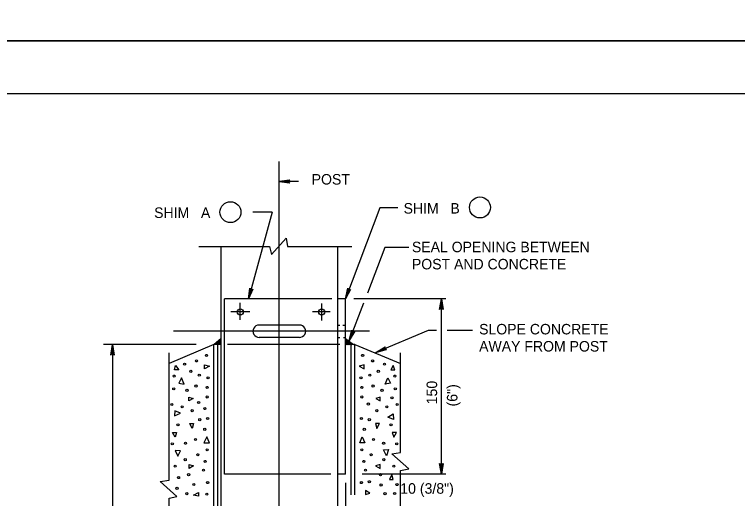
# Model space of a CAD drawing. Extents: x -1958 to 628, y -879 to 309.
# Drawn here: x -1413.6 to -1207.8, y -414.8 to -277.1 of the extents above; entities that cross this region are included whole.
import ezdxf

# ---------------------------------------------------------------- set-up
doc = ezdxf.new("R2010")
doc.units = 0
for name, color, linetype in [('1', 7, 'Continuous'), ('2', 7, 'Continuous'), ('3', 7, 'Continuous'), ('PLT-BNDY', 7, 'Continuous')]:
    doc.layers.add(name, color=color, linetype=linetype)

msp = doc.modelspace()

# ---------------------------------------------------------------- linework, layer by layer
at = {"layer": '1'}
msp.add_line((-1918.39, -299.56), (-1132.39, -299.56), dxfattribs=at)
at = {"layer": '2'}
for p, q in [((-1340.52, -345.33), (-1336.27, -340.7)), ((-1336.27, -340.7), (-1335.89, -343.08)), ((-1361.14, -343.08), (-1341.02, -343.08)), ((-1354.77, -458.72), (-1354.77, -343.08)), ((-1341.02, -343.08), (-1340.52, -345.33)), ((-1335.89, -343.08), (-1317.64, -343.08)), ((-1321.64, -519.58), (-1321.64, -343.08)), ((-1323.27, -357.95), (-1353.89, -357.95)), ((-1353.89, -407.83), (-1353.89, -357.95)), ((-1319.39, -357.95), (-1321.64, -357.95)), ((-1319.39, -407.83), (-1319.39, -357.95)), ((-1349.39, -363.95), (-1349.39, -359.08)), ((-1326.14, -364.08), (-1326.14, -359.33)), ((-1346.64, -361.7), (-1352.02, -361.7)), ((-1323.77, -361.7), (-1328.77, -361.7)), ((-1332.52, -365.45), (-1344.02, -365.45)), ((-1321.64, -365.45), (-1321.02, -365.45)), ((-1320.14, -365.45), (-1319.39, -365.45)), ((-1312.64, -367.2), (-1368.39, -367.2)), ((-1354.77, -369.2), (-1356.77, -370.95)), ((-1354.77, -369.45), (-1356.52, -370.95)), ((-1354.77, -369.83), (-1356.27, -370.95)), ((-1354.77, -370.08), (-1355.89, -370.83)), ((-1354.77, -370.33), (-1355.64, -370.95)), ((-1332.52, -368.95), (-1344.02, -368.95)), ((-1321.64, -368.95), (-1321.02, -368.95)), ((-1320.02, -368.95), (-1319.39, -368.95)), ((-1319.39, -369.2), (-1317.14, -370.95)), ((-1319.39, -369.45), (-1317.52, -370.95)), ((-1319.39, -369.83), (-1317.89, -370.95)), ((-1319.39, -370.08), (-1318.27, -370.95)), ((-1319.39, -370.33), (-1318.52, -370.95)), ((-1356.89, -370.95), (-1369.64, -376.33)), ((-1354.77, -370.95), (-1356.89, -370.95)), ((-1356.89, -458.72), (-1356.89, -370.95)), ((-1355.77, -458.63), (-1355.77, -370.95)), ((-1354.77, -370.58), (-1355.27, -370.83)), ((-1354.77, -370.83), (-1355.02, -370.95)), ((-1321.02, -370.95), (-1353.02, -370.95)), ((-1319.39, -370.58), (-1318.89, -370.95)), ((-1319.39, -370.83), (-1319.27, -370.95)), ((-1316.77, -370.95), (-1319.39, -370.95)), ((-1317.77, -413.7), (-1317.77, -370.95)), ((-1316.77, -370.95), (-1303.77, -376.33)), ((-1316.77, -413.7), (-1316.77, -370.95)), ((-1369.64, -409.58), (-1369.64, -373.33)), ((-1303.77, -401.7), (-1303.77, -373.33)), ((-1306.27, -402.08), (-1303.77, -401.7)), ((-1301.39, -406.33), (-1306.27, -402.08)), ((-1303.77, -406.83), (-1301.39, -406.33)), ((-1303.77, -451.2), (-1303.77, -406.83)), ((-1323.64, -407.83), (-1353.89, -407.83)), ((-1319.39, -407.83), (-1321.64, -407.83)), ((-1372.14, -409.95), (-1369.64, -409.58)), ((-1367.39, -414.2), (-1372.14, -409.95)), ((-1369.64, -414.7), (-1367.39, -414.2)), ((-1369.64, -460.08), (-1369.64, -414.7))]:
    msp.add_line(p, q, dxfattribs=at)
for points in [[(-1366.89, -378.2), (-1368.14, -378.2), (-1367.77, -376.95)], [(-1359.52, -377.83), (-1359.52, -376.7), (-1358.14, -377.08)], [(-1314.14, -377.83), (-1314.14, -376.7), (-1315.52, -377.08)], [(-1306.52, -378.2), (-1305.39, -378.2), (-1305.89, -376.95)], [(-1366.89, -381.95), (-1365.39, -382.2), (-1366.14, -380.45)], [(-1306.64, -381.95), (-1308.14, -382.2), (-1307.39, -380.45)], [(-1364.02, -386.95), (-1364.02, -385.95), (-1362.77, -386.33)], [(-1309.52, -386.95), (-1309.52, -385.95), (-1310.77, -386.33)], [(-1368.02, -389.83), (-1368.14, -391.2), (-1366.39, -390.45)], [(-1305.89, -390.7), (-1305.77, -392.33), (-1307.39, -391.58)], [(-1363.77, -393.45), (-1362.64, -393.45), (-1363.02, -394.83)], [(-1309.77, -393.45), (-1310.89, -393.45), (-1310.52, -394.83)], [(-1368.64, -395.95), (-1367.52, -395.95), (-1367.89, -397.33)], [(-1359.77, -398.95), (-1358.14, -398.95), (-1358.89, -397.2)], [(-1313.89, -398.95), (-1315.39, -398.95), (-1314.64, -397.2)], [(-1304.89, -395.95), (-1306.14, -395.95), (-1305.64, -397.33)], [(-1366.39, -401.2), (-1367.89, -401.08), (-1367.14, -402.7)], [(-1308.64, -400.95), (-1307.14, -400.83), (-1307.77, -402.58)], [(-1363.89, -406.2), (-1363.89, -405.08), (-1362.64, -405.45)], [(-1309.52, -406.2), (-1309.52, -405.08), (-1310.89, -405.45)], [(-1306.89, -409.33), (-1305.89, -409.33), (-1306.27, -407.95)], [(-1361.27, -413.08), (-1361.27, -414.08), (-1362.64, -413.83)], [(-1313.77, -412.45), (-1313.77, -413.58), (-1312.52, -413.2)]]:
    msp.add_lwpolyline(points, close=True, dxfattribs=at)
for centre, radius in [((-1349.36, -361.69), 0.856), ((-1326.19, -361.69), 0.856), ((-1359.01, -374.05), 0.301), ((-1314.54, -374.05), 0.301), ((-1365.22, -376.56), 0.301), ((-1361.85, -375.62), 0.301), ((-1311.71, -375.62), 0.301), ((-1308.34, -376.56), 0.301), ((-1363.46, -378.58), 0.301), ((-1310.09, -378.58), 0.301), ((-1368.18, -379.93), 0.301), ((-1361.04, -379.66), 0.301), ((-1358.54, -380.43), 0.301), ((-1315.02, -380.43), 0.301), ((-1312.52, -379.66), 0.301), ((-1305.38, -379.93), 0.301), ((-1361.98, -382.76), 0.301), ((-1311.58, -382.76), 0.301), ((-1368.31, -383.57), 0.301), ((-1364.54, -383.97), 0.301), ((-1358.78, -383.15), 0.301), ((-1314.78, -383.15), 0.301), ((-1309.02, -383.97), 0.301), ((-1305.24, -383.57), 0.301), ((-1358.78, -385.87), 0.301), ((-1314.78, -385.87), 0.301), ((-1306.19, -386.13), 0.301), ((-1368.85, -388.02), 0.301), ((-1365.89, -388.69), 0.301), ((-1361.23, -387.43), 0.301), ((-1359.45, -389.18), 0.301), ((-1312.92, -387.88), 0.301), ((-1307.67, -388.69), 0.301), ((-1304.7, -388.02), 0.301), ((-1363.06, -389.77), 0.301), ((-1310.5, -389.77), 0.301), ((-1360.91, -392.33), 0.301), ((-1358.66, -392.02), 0.301), ((-1314.9, -392.02), 0.301), ((-1312.65, -392.33), 0.301), ((-1367.1, -393.82), 0.301), ((-1359.49, -395.09), 0.301), ((-1314.07, -395.09), 0.301), ((-1306.46, -393.82), 0.301), ((-1368.72, -399.21), 0.301), ((-1364.98, -399.04), 0.301), ((-1362.12, -397.99), 0.301), ((-1311.44, -397.99), 0.301), ((-1308.57, -399.04), 0.301), ((-1304.84, -399.21), 0.301), ((-1358.78, -400.89), 0.301), ((-1314.78, -400.89), 0.301), ((-1361.44, -402.31), 0.301), ((-1312.11, -402.31), 0.301), ((-1367.91, -405.54), 0.301), ((-1365.03, -403.7), 0.301), ((-1359.37, -404.2), 0.301), ((-1314.19, -404.2), 0.301), ((-1308.53, -403.7), 0.301), ((-1305.65, -405.54), 0.301), ((-1359.84, -406.68), 0.301), ((-1313.72, -406.68), 0.301), ((-1366.93, -408.81), 0.301), ((-1364.07, -407.97), 0.301), ((-1309.48, -407.97), 0.301), ((-1367.37, -411.87), 0.301), ((-1362.6, -410.78), 0.301), ((-1358.66, -410.23), 0.301), ((-1314.9, -410.23), 0.301), ((-1312.65, -409.99), 0.301), ((-1309.3, -410.9), 0.301), ((-1304.77, -410.8), 0.301), ((-1364.56, -413.38), 0.301), ((-1358.9, -413.54), 0.301), ((-1308.17, -413.38), 0.301), ((-1305.44, -413.35), 0.301)]:
    msp.add_circle(centre, radius, dxfattribs=at)
for centre, start, end in [((-1344.04, -367.17), 89.2551, 271.9772), ((-1332.5, -367.17), 268.0228, 90.7449)]:
    msp.add_arc(centre, 1.74, start, end, dxfattribs=at)
at = {"layer": '3'}
for p, q in [((-1338.27, -463.95), (-1338.27, -318.87)), ((-1332.77, -324.58), (-1338.27, -324.58)), ((-1340.27, -333.33), (-1347.02, -357.95)), ((-1340.27, -333.33), (-1345.77, -333.33)), ((-1309.64, -332.08), (-1319.39, -357.95)), ((-1304.52, -332.08), (-1309.64, -332.08)), ((-1308.27, -343.33), (-1313.14, -356.33)), ((-1301.39, -343.33), (-1308.27, -343.33)), ((-1290.89, -357.95), (-1317.02, -357.95)), ((-1292.14, -407.83), (-1292.14, -357.95)), ((-1314.27, -359.2), (-1318.39, -369.83)), ((-1295.89, -366.95), (-1310.77, -373.2)), ((-1293.52, -366.95), (-1295.89, -366.95)), ((-1283.27, -366.95), (-1290.52, -366.95)), ((-1361.89, -370.95), (-1388.26, -370.95)), ((-1385.76, -370.95), (-1385.76, -520.83)), ((-1290.89, -407.83), (-1314.64, -407.83)), ((-1319.39, -410.33), (-1319.39, -426.2))]:
    msp.add_line(p, q, dxfattribs=at)
for points in [[(-1335.39, -324.95), (-1335.52, -324.7), (-1338.27, -324.58), (-1335.39, -324.95), (-1335.27, -325.08), (-1338.27, -324.58), (-1335.52, -324.45), (-1335.39, -324.2), (-1338.27, -324.58), (-1335.27, -324.08), (-1335.39, -324.2)], [(-1345.89, -355.33), (-1346.14, -355.33), (-1347.02, -357.95), (-1345.89, -355.33), (-1345.77, -355.2), (-1347.02, -357.95), (-1346.39, -355.33), (-1346.64, -355.08), (-1347.02, -357.95), (-1346.64, -354.95), (-1346.64, -355.08)], [(-1318.14, -355.45), (-1318.39, -355.45), (-1319.39, -357.95), (-1318.14, -355.45), (-1318.02, -355.33), (-1319.39, -357.95), (-1318.52, -355.33), (-1318.77, -355.2), (-1319.39, -357.95), (-1318.77, -354.95), (-1318.77, -355.2)], [(-1292.52, -360.83), (-1292.39, -360.7), (-1292.14, -357.95), (-1292.52, -360.83), (-1292.64, -360.95), (-1292.14, -357.95), (-1292.02, -360.7), (-1291.77, -360.83), (-1292.14, -357.95), (-1291.64, -360.95), (-1291.77, -360.83)], [(-1316.89, -367.33), (-1317.14, -367.33), (-1318.39, -369.83), (-1316.89, -367.33), (-1316.77, -367.2), (-1318.39, -369.83), (-1317.52, -367.2), (-1317.64, -367.08), (-1318.39, -369.83), (-1317.64, -366.83), (-1317.64, -367.08)], [(-1386.14, -373.83), (-1386.01, -373.7), (-1385.76, -370.95), (-1386.14, -373.83), (-1386.26, -373.95), (-1385.76, -370.95), (-1385.64, -373.7), (-1385.39, -373.7), (-1385.76, -370.95), (-1385.26, -373.95), (-1385.39, -373.7)], [(-1307.89, -372.33), (-1308.14, -372.2), (-1310.77, -373.2), (-1307.89, -372.33), (-1307.77, -372.45), (-1310.77, -373.2), (-1308.27, -371.95), (-1308.27, -371.83), (-1310.77, -373.2), (-1308.14, -371.58), (-1308.27, -371.83)], [(-1291.77, -404.95), (-1292.02, -404.95), (-1292.14, -407.83), (-1291.77, -404.95), (-1291.64, -404.83), (-1292.14, -407.83), (-1292.27, -404.95), (-1292.52, -404.95), (-1292.14, -407.83), (-1292.64, -404.83), (-1292.52, -404.95)]]:
    msp.add_lwpolyline(points, dxfattribs=at)
for centre in [(-1281.15, -331.95), (-1352.17, -333.3)]:
    msp.add_circle(centre, 2.98, dxfattribs=at)
at = {"layer": 'PLT-BNDY'}
for points in [[(-1958.39, 309.44), (-1117.39, 309.44), (-1117.39, -284.56), (-1958.39, -284.56)], [(-1958.39, -284.56), (-1117.39, -284.56), (-1117.39, -878.56), (-1958.39, -878.56)]]:
    msp.add_lwpolyline(points, close=True, dxfattribs=at)

# ---------------------------------------------------------------- texts
at = {"layer": '2'}
for s, p in [('  POST', (-1331.27, -325.45)), ('SHIM   B ', (-1302.89, -333.7)), ('SHIM   A ', (-1373.89, -334.95)), ('SEAL OPENING BETWEEN', (-1300.52, -344.7)), ('POST AND CONCRETE', (-1300.52, -349.58)), ('SLOPE CONCRETE', (-1281.39, -368.08)), ('AWAY FROM POST', (-1281.39, -372.95))]:
    msp.add_text(s, height=2.988, dxfattribs=at).set_placement(p)
at = {"layer": '3'}
for s, p in [('150 ', (-1293.34, -387.97)), ('(6")', (-1287.56, -388.57))]:
    msp.add_text(s, height=3, rotation=90, dxfattribs=at).set_placement(p)
msp.add_text(' 10 (3/8")', height=3, dxfattribs=at).set_placement((-1304.95, -413.4))

doc.saveas('drawing.dxf')
